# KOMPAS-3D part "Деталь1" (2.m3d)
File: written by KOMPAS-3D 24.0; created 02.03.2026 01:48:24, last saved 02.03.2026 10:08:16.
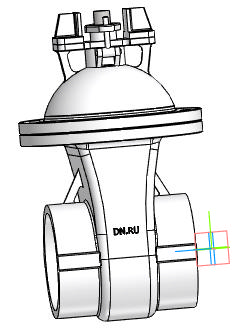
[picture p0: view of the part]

Document properties: Автор: R2D2; Полное имя файла: E:\Работа\Зайцев\GVWR3131M-2W-F-S Задвижка клиновая с выдвижным штоком DN.ru Ду50-200 Ру63\DN150\исходные материалы\2.m3d

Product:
- Body: Твердое тело1  | qty 1
    Масса: 1.47915
- Part/product: Деталь1
    Масса: 1.47915
    additional columns: Типовые

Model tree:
1. Твердое тело1  (labels: Твердое тело1)
2. Эскиз:1
3. Элемент выдавливания:2
     Расстояние 1 = 500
